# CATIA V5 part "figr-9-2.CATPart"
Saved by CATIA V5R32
Part number: Part1
Bounding box of the stored display mesh (mm): x -25 to 69.61, y -139.735 to 0, z 0 to 45
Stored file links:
  D:\PROJECTS\Project 2022\CATIA V5 6R 2022\Resources\Part Files\c09_catia_v5_6r2022_prt\c09_catia_v5_6r2022_prt\figr-9-2.CATPart
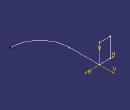
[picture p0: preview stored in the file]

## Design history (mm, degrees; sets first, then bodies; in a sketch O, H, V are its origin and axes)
Body1 (main body)
  Sketch1 on xy-plane, origin (0, 0, 0), H (1, 0, 0), V (0, 1, 0)
    line L1 (0, 0) -> (0, -70.1255)
    arc A1 centre (69.6095, -70.1255) radius 69.6095 from (0, -70.1255) to (69.6095, -139.7351) ccw
    vertical: L1 V
    tangency: A1 L1
  Sketch2 on zx-plane, origin (0, 0, 0), H (-1, 0, 0), V (0, 0, 1)
    point P1 (0, 0)
    line L1 (0, 0) -> (25, 0)
    line L2 (25, 0) -> (25, 45)
    line L3 (25, 45) -> (0, 45)
    line L4 (0, 45) -> (0, 0)
    length L3 = 25
    length L2 = 45
    coincidence: P1 H, P1 O
    horizontal: L1 H, L3 H
    vertical: L2 V, L4 V
  Rib1: profile Sketch2, centre curve Sketch1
